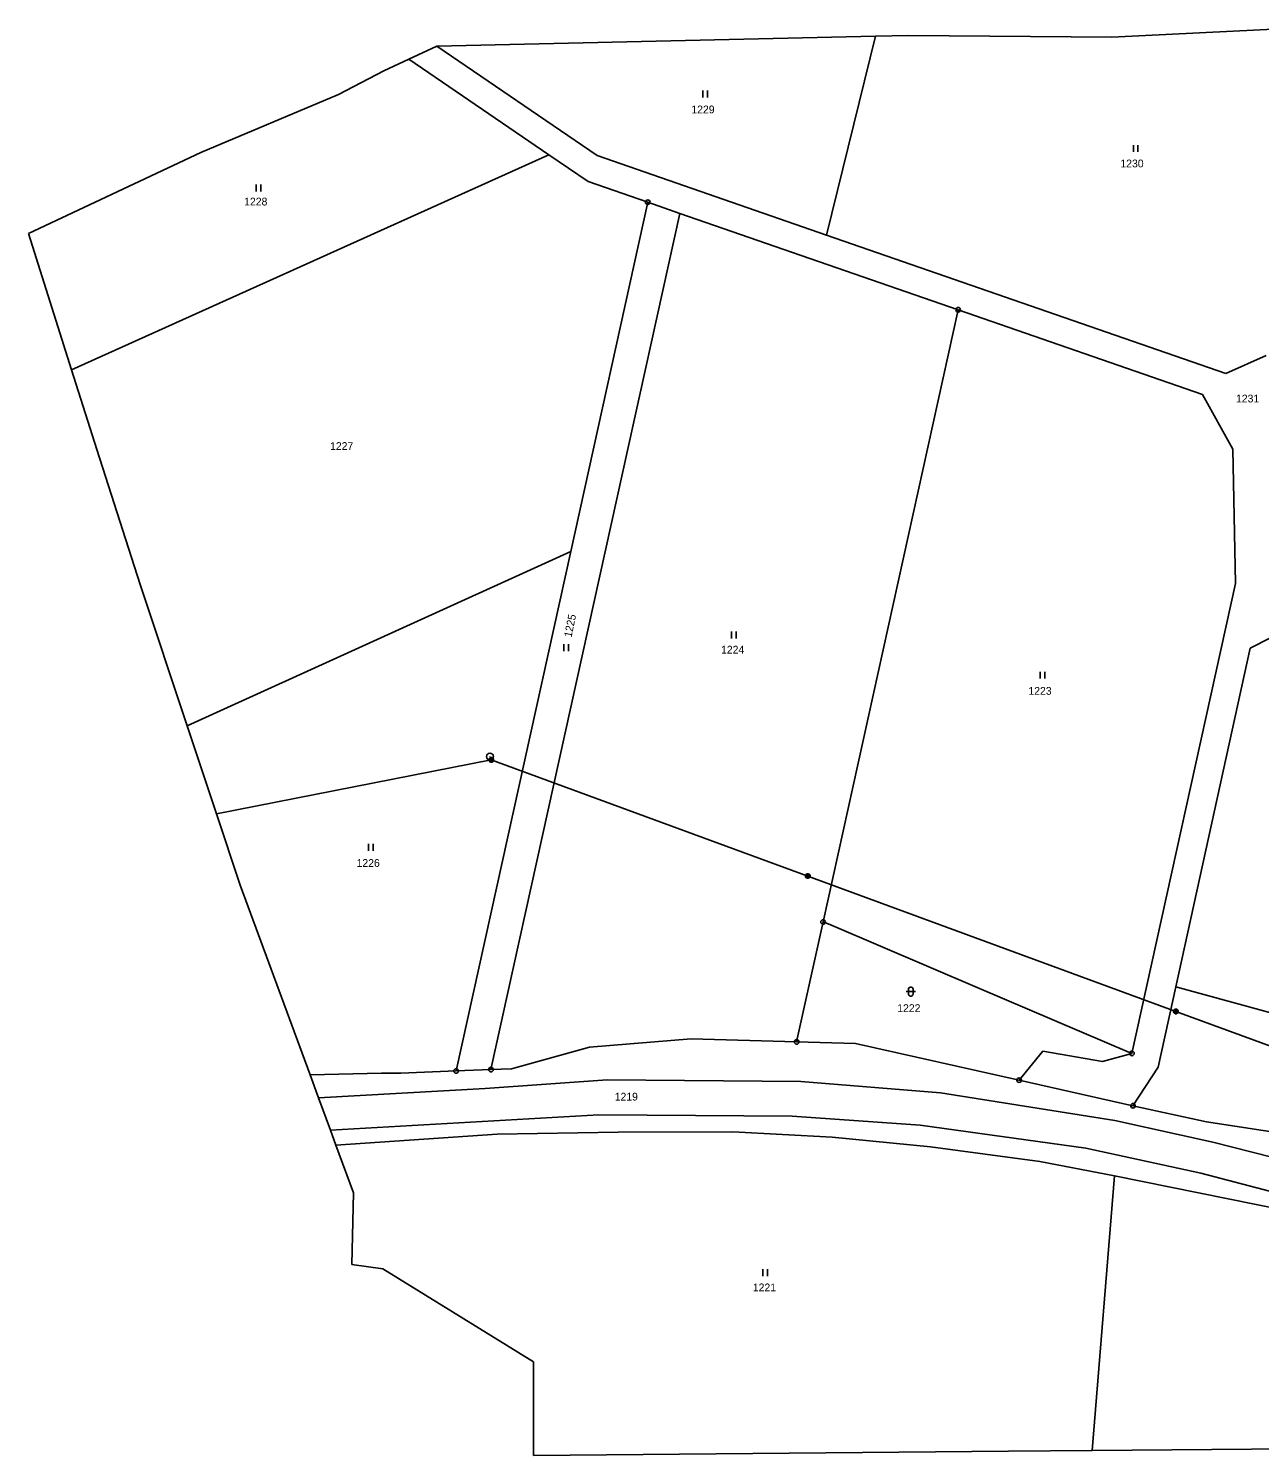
# Model space of a CAD drawing. Extents: x -796130 to -793145, y -1109506 to -1106267.
# Drawn here: x -795231.1 to -794962.6, y -1109482.2 to -1109171 of the extents above; entities that cross this region are included whole.
import ezdxf

# ---------------------------------------------------------------- set-up
doc = ezdxf.new("R2010")
doc.units = 0
for name, color, linetype in [('Vrstva 1', 7, 'Continuous'), ('Vrstva 12', 7, 'Continuous'), ('Vrstva 14', 7, 'Continuous'), ('Vrstva 2', 7, 'Continuous'), ('Vrstva 23', 7, 'Continuous'), ('Vrstva 26', 7, 'Continuous'), ('Vrstva 28', 7, 'Continuous'), ('Vrstva 4', 7, 'Continuous')]:
    doc.layers.add(name, color=color, linetype=linetype)

msp = doc.modelspace()

# ---------------------------------------------------------------- linework, layer by layer
at = {"layer": 'Vrstva 1'}
for p, q in [((-795046.3, -1109172.68), (-795057, -1109216.03)), ((-795141.99, -1109174.79), (-795107.08, -1109198.68)), ((-795117.58, -1109198.51), (-795148.11, -1109177.65)), ((-795221.7, -1109245.4), (-795117.58, -1109198.51)), ((-795109.04, -1109204.35), (-795117.58, -1109198.51)), ((-795107.08, -1109198.68), (-795057, -1109216.03)), ((-795109.04, -1109204.35), (-795096.02, -1109208.86)), ((-795096.02, -1109208.86), (-795112.83, -1109285.04)), ((-795096.02, -1109208.86), (-795089, -1109211.29)), ((-795089, -1109211.29), (-795130.21, -1109398.05)), ((-795089, -1109211.29), (-795028.31, -1109232.32)), ((-795057, -1109216.03), (-794969.89, -1109246.22)), ((-795057.77, -1109365.85), (-795028.31, -1109232.32)), ((-795028.31, -1109232.32), (-794975.02, -1109250.79)), ((-794969.89, -1109246.22), (-794961.13, -1109242.3)), ((-794968.41, -1109262.69), (-794975.02, -1109250.79)), ((-794968.41, -1109262.69), (-794967.79, -1109292.06)), ((-795196.47, -1109323.09), (-795112.83, -1109285.04)), ((-795112.83, -1109285.04), (-795137.83, -1109398.35)), ((-794990.4, -1109394.51), (-794967.79, -1109292.06)), ((-794953.46, -1109300.46), (-794964.62, -1109306.1)), ((-794980.8, -1109379.96), (-794964.62, -1109306.1)), ((-795057.77, -1109365.85), (-795063.54, -1109392.01)), ((-795055.8, -1109366.6), (-795057.77, -1109365.85)), ((-795024.19, -1109380.14), (-795055.8, -1109366.6)), ((-794990.4, -1109394.51), (-795024.19, -1109380.14)), ((-794984.65, -1109397.55), (-794980.8, -1109379.96)), ((-794930.67, -1109393.78), (-794980.8, -1109379.96)), ((-795108.73, -1109393.13), (-795086.54, -1109391.37)), ((-795086.54, -1109391.37), (-795063.54, -1109392.01)), ((-795125.72, -1109397.88), (-795108.73, -1109393.13)), ((-795063.54, -1109392.01), (-795050.7, -1109392.36)), ((-795050.7, -1109392.36), (-795015, -1109400.36)), ((-795015, -1109400.36), (-795009.82, -1109394.06)), ((-795009.82, -1109394.06), (-794996.85, -1109396.26)), ((-794996.85, -1109396.26), (-794990.4, -1109394.51)), ((-795130.21, -1109398.05), (-795125.72, -1109397.88)), ((-794990.17, -1109405.93), (-794984.65, -1109397.55)), ((-795169.69, -1109399.21), (-795154.08, -1109398.84)), ((-795154.08, -1109398.84), (-795149.9, -1109398.82)), ((-795149.9, -1109398.82), (-795137.83, -1109398.35)), ((-795137.83, -1109398.35), (-795130.21, -1109398.05)), ((-795015, -1109400.36), (-794990.17, -1109405.93)), ((-794990.17, -1109405.93), (-794974.14, -1109409.46)), ((-794974.14, -1109409.46), (-794949.43, -1109413.22)), ((-794999.06, -1109481.13), (-794994.23, -1109421.19))]:
    msp.add_line(p, q, dxfattribs=at)
for points in [[(-795164.05, -1109414.51), (-795128.9, -1109412.12), (-795102.48, -1109411.68), (-795077.48, -1109411.63), (-795055.78, -1109412.82), (-795034.35, -1109414.86), (-795010.51, -1109418.08), (-794994.23, -1109421.19)], [(-794994.23, -1109421.19), (-794957.19, -1109428.69), (-794940.45, -1109434.05)]]:
    msp.add_lwpolyline(points, dxfattribs=at)
at = {"layer": 'Vrstva 12'}
for p, q in [((-795130.14, -1109330.49), (-795190.1, -1109342.23)), ((-795061.1, -1109355.83), (-795130.14, -1109330.49)), ((-794980.81, -1109385.37), (-795061.1, -1109355.83)), ((-794886.15, -1109420.1), (-794980.81, -1109385.37))]:
    msp.add_line(p, q, dxfattribs=at)
at = {"layer": 'Vrstva 2'}
for p, q in [((-795131.5, -1109402.19), (-795104.84, -1109400.29)), ((-795104.84, -1109400.29), (-795062.62, -1109400.61)), ((-795062.62, -1109400.61), (-795032.14, -1109403.15)), ((-795167.85, -1109404.21), (-795131.5, -1109402.19)), ((-795032.14, -1109403.15), (-794994.16, -1109409.16)), ((-795106.68, -1109407.92), (-795165.25, -1109411.25)), ((-795064.5, -1109408.24), (-795106.68, -1109407.92)), ((-795036.59, -1109410.14), (-795064.5, -1109408.24)), ((-795000.44, -1109415.22), (-795036.59, -1109410.14)), ((-794994.16, -1109409.16), (-794972.72, -1109413.89)), ((-794975.38, -1109420.61), (-795000.44, -1109415.22)), ((-794972.72, -1109413.89), (-794953.08, -1109418.86)), ((-794957.31, -1109425.37), (-794975.38, -1109420.61))]:
    msp.add_line(p, q, dxfattribs=at)
at = {"layer": 'Vrstva 23'}
for p, q in [((-795084.01, -1109186.03), (-795084.01, -1109184.53)), ((-795083.01, -1109184.53), (-795083.01, -1109186.03)), ((-794990.08, -1109197.9), (-794990.08, -1109196.4)), ((-794989.08, -1109196.4), (-794989.08, -1109197.9)), ((-795181.4, -1109206.52), (-795181.4, -1109205.02)), ((-795180.4, -1109205.02), (-795180.4, -1109206.52)), ((-795077.72, -1109304.02), (-795077.72, -1109302.52)), ((-795076.72, -1109302.52), (-795076.72, -1109304.02)), ((-795114.3, -1109306.79), (-795114.3, -1109305.29)), ((-795113.3, -1109305.29), (-795113.3, -1109306.79)), ((-795010.38, -1109312.78), (-795010.38, -1109311.28)), ((-795009.38, -1109311.28), (-795009.38, -1109312.78)), ((-795156.93, -1109350.32), (-795156.93, -1109348.82)), ((-795155.93, -1109348.82), (-795155.93, -1109350.32)), ((-795039.63, -1109381.04), (-795037.63, -1109381.04)), ((-795039.13, -1109380.44), (-795039.03, -1109380.24)), ((-795039.13, -1109381.64), (-795039.13, -1109380.44)), ((-795039.03, -1109381.84), (-795039.13, -1109381.64)), ((-795039.03, -1109380.24), (-795038.93, -1109380.14)), ((-795038.93, -1109381.94), (-795039.03, -1109381.84)), ((-795038.93, -1109380.14), (-795038.73, -1109380.04)), ((-795038.73, -1109382.04), (-795038.93, -1109381.94)), ((-795038.73, -1109380.04), (-795038.53, -1109380.04)), ((-795038.53, -1109382.04), (-795038.73, -1109382.04)), ((-795038.53, -1109380.04), (-795038.33, -1109380.14)), ((-795038.33, -1109381.94), (-795038.53, -1109382.04)), ((-795038.33, -1109380.14), (-795038.23, -1109380.24)), ((-795038.23, -1109381.84), (-795038.33, -1109381.94)), ((-795038.23, -1109380.24), (-795038.13, -1109380.44)), ((-795038.13, -1109381.64), (-795038.23, -1109381.84)), ((-795038.13, -1109380.44), (-795038.13, -1109381.64)), ((-795070.92, -1109443.09), (-795070.92, -1109441.59)), ((-795069.92, -1109441.59), (-795069.92, -1109443.09))]:
    msp.add_line(p, q, dxfattribs=at)
at = {"layer": 'Vrstva 26'}
for p, q in [((-795130.64, -1109330.39), (-795130.54, -1109330.19)), ((-795130.64, -1109330.59), (-795130.64, -1109330.39)), ((-795130.54, -1109330.79), (-795130.64, -1109330.59)), ((-795130.54, -1109330.19), (-795130.44, -1109330.09)), ((-795130.44, -1109330.89), (-795130.54, -1109330.79)), ((-795130.44, -1109330.09), (-795130.24, -1109329.99)), ((-795130.44, -1109330.29), (-795130.44, -1109330.69)), ((-795130.44, -1109330.69), (-795130.24, -1109330.79)), ((-795130.24, -1109330.99), (-795130.44, -1109330.89)), ((-795130.24, -1109329.99), (-795130.04, -1109329.99)), ((-795130.24, -1109330.79), (-795130.24, -1109330.19)), ((-795130.24, -1109330.19), (-795130.04, -1109330.19)), ((-795130.04, -1109330.99), (-795130.24, -1109330.99)), ((-795130.04, -1109329.99), (-795129.84, -1109330.09)), ((-795130.04, -1109330.19), (-795130.04, -1109330.79)), ((-795130.04, -1109330.79), (-795129.84, -1109330.69)), ((-795129.84, -1109330.89), (-795130.04, -1109330.99)), ((-795129.84, -1109330.09), (-795129.74, -1109330.19)), ((-795129.84, -1109330.69), (-795129.84, -1109330.29)), ((-795129.74, -1109330.79), (-795129.84, -1109330.89)), ((-795129.74, -1109330.19), (-795129.64, -1109330.39)), ((-795129.64, -1109330.59), (-795129.74, -1109330.79)), ((-795129.64, -1109330.39), (-795129.64, -1109330.59)), ((-795061.6, -1109355.73), (-795061.5, -1109355.53)), ((-795061.6, -1109355.93), (-795061.6, -1109355.73)), ((-795061.5, -1109356.13), (-795061.6, -1109355.93)), ((-795061.5, -1109355.53), (-795061.4, -1109355.43)), ((-795061.4, -1109356.23), (-795061.5, -1109356.13)), ((-795061.4, -1109355.43), (-795061.2, -1109355.33)), ((-795061.4, -1109355.63), (-795061.4, -1109356.03)), ((-795061.4, -1109356.03), (-795061.2, -1109356.13)), ((-795061.2, -1109356.33), (-795061.4, -1109356.23)), ((-795061.2, -1109355.33), (-795061, -1109355.33)), ((-795061.2, -1109356.13), (-795061.2, -1109355.53)), ((-795061.2, -1109355.53), (-795061, -1109355.53)), ((-795061, -1109356.33), (-795061.2, -1109356.33)), ((-795061, -1109355.33), (-795060.8, -1109355.43)), ((-795061, -1109355.53), (-795061, -1109356.13)), ((-795061, -1109356.13), (-795060.8, -1109356.03)), ((-795060.8, -1109356.23), (-795061, -1109356.33)), ((-795060.8, -1109355.43), (-795060.7, -1109355.53)), ((-795060.8, -1109356.03), (-795060.8, -1109355.63)), ((-795060.7, -1109356.13), (-795060.8, -1109356.23)), ((-795060.7, -1109355.53), (-795060.6, -1109355.73)), ((-795060.6, -1109355.93), (-795060.7, -1109356.13)), ((-795060.6, -1109355.73), (-795060.6, -1109355.93)), ((-794981.31, -1109385.27), (-794981.21, -1109385.07)), ((-794981.31, -1109385.47), (-794981.31, -1109385.27)), ((-794981.21, -1109385.67), (-794981.31, -1109385.47)), ((-794981.21, -1109385.07), (-794981.11, -1109384.97)), ((-794981.11, -1109384.97), (-794980.91, -1109384.87)), ((-794981.11, -1109385.17), (-794981.11, -1109385.57)), ((-794980.91, -1109384.87), (-794980.71, -1109384.87)), ((-794980.91, -1109385.67), (-794980.91, -1109385.07)), ((-794980.91, -1109385.07), (-794980.71, -1109385.07)), ((-794980.71, -1109384.87), (-794980.51, -1109384.97)), ((-794980.71, -1109385.07), (-794980.71, -1109385.67)), ((-794980.51, -1109384.97), (-794980.41, -1109385.07)), ((-794980.51, -1109385.57), (-794980.51, -1109385.17)), ((-794980.41, -1109385.07), (-794980.31, -1109385.27)), ((-794980.31, -1109385.47), (-794980.41, -1109385.67)), ((-794980.31, -1109385.27), (-794980.31, -1109385.47)), ((-794981.11, -1109385.77), (-794981.21, -1109385.67)), ((-794981.11, -1109385.57), (-794980.91, -1109385.67)), ((-794980.91, -1109385.87), (-794981.11, -1109385.77)), ((-794980.71, -1109385.87), (-794980.91, -1109385.87)), ((-794980.71, -1109385.67), (-794980.51, -1109385.57)), ((-794980.51, -1109385.77), (-794980.71, -1109385.87)), ((-794980.41, -1109385.67), (-794980.51, -1109385.77))]:
    msp.add_line(p, q, dxfattribs=at)
at = {"layer": 'Vrstva 28'}
for centre, radius in [((-795096.02, -1109208.86), 0.5), ((-795096.02, -1109208.86), 0.01), ((-795028.31, -1109232.32), 0.5), ((-795028.31, -1109232.32), 0.01), ((-795130.44, -1109329.78), 0.75), ((-795130.44, -1109329.78), 0.01), ((-795057.77, -1109365.85), 0.5), ((-795057.77, -1109365.85), 0.01), ((-795063.54, -1109392.01), 0.5), ((-795063.54, -1109392.01), 0.01), ((-794990.4, -1109394.51), 0.5), ((-794990.4, -1109394.51), 0.01), ((-795137.83, -1109398.35), 0.5), ((-795130.21, -1109398.05), 0.5), ((-795137.83, -1109398.35), 0.01), ((-795130.21, -1109398.05), 0.01), ((-795015, -1109400.36), 0.5), ((-795015, -1109400.36), 0.01), ((-794990.17, -1109405.93), 0.5), ((-794990.17, -1109405.93), 0.01)]:
    msp.add_circle(centre, radius, dxfattribs=at)
at = {"layer": 'Vrstva 4'}
for p, q in [((-795141.99, -1109174.79), (-795046.3, -1109172.68)), ((-795046.3, -1109172.68), (-795039.14, -1109172.52)), ((-794994.78, -1109172.87), (-795039.14, -1109172.52)), ((-794956.56, -1109170.98), (-794994.78, -1109172.87)), ((-795148.11, -1109177.65), (-795141.99, -1109174.79)), ((-795153.55, -1109180.19), (-795148.11, -1109177.65)), ((-795153.55, -1109180.19), (-795163.46, -1109185.4)), ((-795163.46, -1109185.4), (-795193.51, -1109198)), ((-795193.51, -1109198), (-795231.09, -1109215.69)), ((-795231.09, -1109215.69), (-795221.7, -1109245.4)), ((-795221.7, -1109245.4), (-795216.2, -1109262.81)), ((-795216.2, -1109262.81), (-795206.72, -1109292.26)), ((-795206.72, -1109292.26), (-795196.47, -1109323.09)), ((-795190.1, -1109342.23), (-795196.47, -1109323.09)), ((-795184.91, -1109357.85), (-795190.1, -1109342.23)), ((-795169.69, -1109399.21), (-795184.91, -1109357.85)), ((-795167.85, -1109404.21), (-795169.69, -1109399.21)), ((-795165.25, -1109411.25), (-795167.85, -1109404.21)), ((-795164.05, -1109414.51), (-795165.25, -1109411.25)), ((-795164.05, -1109414.51), (-795160.22, -1109424.91)), ((-795160.6, -1109440.53), (-795160.22, -1109424.91)), ((-795153.78, -1109441.49), (-795160.6, -1109440.53)), ((-795153.78, -1109441.49), (-795120.95, -1109461.8)), ((-795120.97, -1109482.21), (-795120.95, -1109461.8)), ((-795120.97, -1109482.21), (-795017.33, -1109481.29)), ((-794999.06, -1109481.13), (-795017.33, -1109481.29)), ((-794999.06, -1109481.13), (-794951.09, -1109480.71))]:
    msp.add_line(p, q, dxfattribs=at)

# ---------------------------------------------------------------- texts
at = {"layer": 'Vrstva 14'}
for s, p in [('1229', (-795086.499, -1109189.48)), ('1230', (-794992.909, -1109201.26)), ('1228', (-795184.049, -1109209.57)), ('1231', (-794967.693, -1109252.53)), ('1227', (-795165.316, -1109262.9)), ('1224', (-795080.025, -1109307.31)), ('1223', (-795012.979, -1109316.29)), ('1226', (-795159.529, -1109353.84)), ('1222', (-795041.589, -1109385.49)), ('1219', (-795103.223, -1109404.8)), ('1221', (-795073.093, -1109446.41))]:
    msp.add_text(s, height=1.7, dxfattribs=at).set_placement(p)
msp.add_text('1225', height=1.7, rotation=78.3, dxfattribs=at).set_placement((-795112.65, -1109303.871))

doc.saveas('drawing.dxf')
